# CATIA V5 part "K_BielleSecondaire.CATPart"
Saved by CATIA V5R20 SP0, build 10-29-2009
Part number: Bielle_secondaire
Bounding box of the stored display mesh (mm): x -415 to 15, y -20 to -5, z 108.628 to 189.529
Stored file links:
  G:\Khaled_CFAO_2011\ST2M\ST2M_GR2\jcoetard\Khaled\CAD_CATIA\K_BielleSecondaire.CATPart
  J:\Thinkmotion\Thinkmotion_COETARD\Maquette_catia\Maquette_catia_R20_Licence_education\jcharlescoetard.CATPRODUCT\Assemblage_Pince_Prehension_Mors_Paralleles.CATProduct
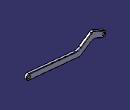
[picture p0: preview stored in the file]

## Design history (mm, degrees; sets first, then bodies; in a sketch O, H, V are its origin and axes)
Set1
  Plane1 "Plan_bielle_secondaire": linked copy from another document
  Point1: linked copy from another document
  Point2: linked copy from another document
Body1 (main body)
  Sketch1 on Plane1, origin (0, -5, 0), H (-1, 0, 0), V (0, 0, 1)
    construction line L1 (0, 150) -> (271.021, 123.6284)
    point P2 (271.021, 123.6284)
    line L2 (1.4527, 164.9295) -> (252.5494, 140.4966)
    line L3 (269.5683, 108.6989) -> (-1.4527, 135.0705)
    arc A1 centre (0, 150) radius 15 from (-1.4527, 135.0705) to (1.4527, 164.9295) cw
    construction line L4 (271.021, 123.6284) -> (345.2436, 174.5303)
    point P6 (271.021, 123.6284)
    point P7 (345.2436, 174.5303)
    line L5 (279.0464, 147.3208) -> (336.76, 186.9008)
    line L6 (328.2868, 144.7128) -> (279.5047, 111.258)
    arc A2 centre (345.2436, 174.5303) radius 15 from (336.76, 186.9008) to (351.3762, 188.2194) cw
    arc A3 centre (271.021, 123.6284) radius 15 from (279.5047, 111.258) to (269.5683, 108.6989) cw
    construction line L7 (345.2436, 174.5303) -> (400, 150)
    point P10 (345.2436, 174.5303)
    line L8 (351.3762, 188.2194) -> (406.1326, 163.6891)
    line L9 (393.8674, 136.3109) -> (367.2634, 148.2292)
    arc A4 centre (400, 150) radius 15 from (406.1326, 163.6891) to (393.8674, 136.3109) cw
    arc A5 centre (256.4233, 180.3086) radius 40 from (279.0464, 147.3208) to (252.5494, 140.4966) cw
    point P17 (256.4233, 180.3086)
    arc A6 centre (350.9099, 111.725) radius 40 from (367.2634, 148.2292) to (328.2868, 144.7128) ccw
    point P20 (350.9099, 111.725)
    reference projected point E1 (0, 150) from Point1
    reference projected point E2 (400, 150) from Point2
    distance L3 L2 = 30
    distance L5 L6 = 30
    distance L9 L8 = 30
    radius A5 = 40
    distance P6 P17 = 58.5298
    radius A6 = 40
    distance P10 P20 = 63.0604
    length L4 = 90
    length L7 = 60
    tangency: A1 L2, A1 L3, A2 L5, A3 L5, A2 L6, A3 L6, A4 L8, A4 L9, A5 L5, A5 L2, A6 L9, A6 L6, A2 L8, A3 L3
    coincidence: P6 P2, P10 P7
    concentricity: A1 E1, A4 E2
  Pad1: profile Sketch1, direction (0, -1, 0), length 15
  Sketch2 on end face of Pad1, origin (0, -20, 180), H (1, 0, 0), V (0, 0, 1)
    point P1 (0, -30)
    reference projected point E1 (0, -30) from Point1
    coincidence: E1 P1
  Hole1: placed by Sketch2, at (0, -20, 150) direction (0, 1, 0), diameter 10, depth 20
  Sketch3 on end face of Pad1, origin (-350, -20, 180), H (1, 0, 0), V (0, 0, 1)
    point P1 (-50, -30)
    reference projected point E1 (-50, -30) from Point2
    coincidence: E1 P1
  Hole2: placed by Sketch3, at (-400, -20, 150) direction (0, 1, 0), diameter 10, depth 20
  Fillet1: radius 2, on start face of Pad1; end face of Pad1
